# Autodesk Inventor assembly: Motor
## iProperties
Created: 2003-12
Part Number: Motor
Document SubType Name: Baugruppe
Designer: Ulrich
Control State: 0
Master: False
Checked Out: False
Shininess: 20.0
Angle Display Precision: 2
Document Length Units: 11269
Document Angle Units: 11279
Document Time Units: 11290
Document Mass Units: 11283
Document Length Units Precision: 3
Document Angle Units Precision: 2
Density: 0.0
Volumn: 0.0
Area: 0.0
PropertySet Name: Model Information
Author: Ulrich
